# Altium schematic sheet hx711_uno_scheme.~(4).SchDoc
size A4
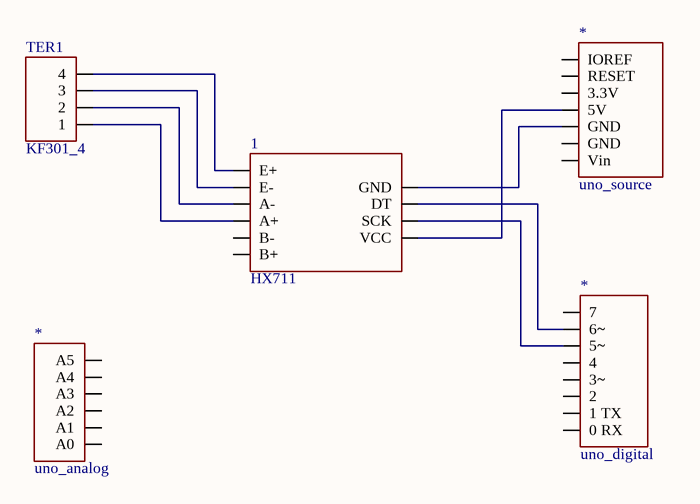
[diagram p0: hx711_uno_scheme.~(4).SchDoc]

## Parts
(Parts that share a designator on the sheet are numbered #1, #2 ... from top to bottom, then left to right.)
1  HX711  [HX711]
*#1  uno_source  [uno_source]
*#2  uno_digital  [uno_digital]
*#3  uno_analog  [uno_analog]
TER1  KF301_4  [KF304_4]

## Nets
Net1_1: 1.1(E+) TER1.4
Net1_2: 1.2(E-) TER1.3
Net1_3: 1.3(A-) TER1.2
Net1_4: 1.4(A+) TER1.1
Net1_7: 1.7(GND) *#1.2(GND)
Net1_8: 1.8(DT) *#2.6(6~)
Net1_9: 1.9(SCK) *#2.?1(5~)
Net1_10: 1.10(VCC) *#1.3(5V)

Not connected (* = marked no-connect by the designer): 1 5(B-) 6(B+); *#1 0(Vin) 1(GND) 4(3.3V) 5(RESET) 6(IOREF); *#2 0(0_RX) 1(1_TX_) 2 3(3~) 4 7; *#3 0(A0) 1(A1) 2(A2) 3(A3) 4(A4) 5(A5)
